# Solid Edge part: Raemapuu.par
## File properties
Author: Kasutaja
Template: Iso Metric Part.par
Last saved by: Kasutaja
Revision: 8
Application: Solid Edge
Accuracy: 0,990
Username: Kasutaja
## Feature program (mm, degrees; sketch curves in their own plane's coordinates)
sketch for "unnamed Protrusion 1" plane through (0, 0, 0) normal (0, -1, 0) x-axis (1, 0, 0)
  line (200, 7.5) -> (-200, 7.5)
  arc centre (-200, 83.2634) radius 75.7634 from (-200, 7.5) to (-269.895, 112.5) cw
  line (-284.895, 112.5) -> (-269.895, 112.5)
  arc centre (-200, 82.5298) radius 90.0298 from (-284.895, 112.5) to (-200, -7.5) ccw
  line (-200, -7.5) -> (200, -7.5)
  arc centre (200, 176.3194) radius 183.8194 from (382.8564, 157.5284) to (200, -7.5) cw
  arc centre (200, 176.323) radius 168.823 from (200, 7.5) to (368.7797, 172.5) ccw
extrude "unnamed Protrusion 1" add finite 12 symmetric
sketch for "ExtrudedCutout_1" #1 plane through (0, 0, 7.5) normal (0, 0, 1) x-axis (1, 0, 0)
  circle centre (-120, 0) radius 2.5
sketch for "ExtrudedCutout_1" #2 plane through (0, 0, 7.5) normal (0, 0, 1) x-axis (1, 0, 0)
  circle centre (0, 0) radius 2.5
sketch for "ExtrudedCutout_1" #3 plane through (0, 0, 7.5) normal (0, 0, 1) x-axis (1, 0, 0)
  circle centre (120, 0) radius 2.5
extrude "ExtrudedCutout_1" cut finite 0.01 symmetric
chamfer "Chamfer_1" setback 3
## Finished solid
Body 1: solid body, 22 faces, 44 edges, 24 vertices.
  Faces by surface: plane 10, cylinder 8, cone 4
  Edges by curve: circle 20, line 20, intersection 4
Bounding box of the edges (mm): 688.108 x 12.000 x 194.319, from (-290.0298, -6, -7.5) to (398.0777, 6, 186.8191).
Cylindrical faces by radius (mm): R2.5 x3, R14.6509 x1, R75.7634 x1, R90.0298 x1, R168.823 x1, R183.8194 x1
Conical faces (half-angle, radius in mm at the cone's reference point): 45 deg R87.0298 x1, 45 deg R90.0298 x1, 45 deg R180.8194 x1, 45 deg R183.8194 x1
Planar faces by outward normal: +y 1, +z 5, -y 1, -z 1, oblique 2
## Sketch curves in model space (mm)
spline (368.7691, 6, 170.0825) -> (368.7604, 6, 170.0634) -> (368.7517, 6, 170.0443)
spline (368.8073, 6, 170.0895) -> (368.7882, 6, 170.086) -> (368.7691, 6, 170.0825)
spline (368.849, 6, 170.1242) -> (368.8282, 6, 170.1069) -> (368.8073, 6, 170.0895)
spline (368.8768, 6, 170.0895) -> (368.8629, 6, 170.1069) -> (368.849, 6, 170.1242)
spline (368.8838, 6, 170.0686) -> (368.8803, 6, 170.079) -> (368.8768, 6, 170.0895)
spline (368.9672, 6, 169.9713) -> (368.9255, 6, 170.02) -> (368.8838, 6, 170.0686)
spline (368.9811, 6, 169.8914) -> (368.9741, 6, 169.9313) -> (368.9672, 6, 169.9713)
spline (369.2418, 6, 169.5612) -> (369.174, 6, 169.6442) -> (368.9811, 6, 169.8914)
spline (369.5928, 6, 169.3492) -> (369.4147, 6, 169.4174) -> (369.2418, 6, 169.5612)
spline (369.7179, 6, 169.3839) -> (369.6554, 6, 169.3665) -> (369.5928, 6, 169.3492)
spline (369.7909, 6, 169.9956) -> (369.7596, 6, 169.6702) -> (369.7179, 6, 169.3839)
spline (369.6588, 6, 170.3015) -> (369.7249, 6, 170.1486) -> (369.7909, 6, 169.9956)
spline (369.7179, 6, 170.4544) -> (369.6884, 6, 170.378) -> (369.6588, 6, 170.3015)
spline (369.6588, 6, 170.8055) -> (369.6636, 6, 170.6443) -> (369.7179, 6, 170.4544)
spline (369.5789, 6, 170.8993) -> (369.6189, 6, 170.8524) -> (369.6588, 6, 170.8055)
spline (369.6032, 6, 170.9584) -> (369.5911, 6, 170.9288) -> (369.5789, 6, 170.8993)
spline (369.5441, 6, 171.0279) -> (369.5737, 6, 170.9931) -> (369.6032, 6, 170.9584)
spline (369.565, 6, 171.0905) -> (369.5546, 6, 171.0592) -> (369.5441, 6, 171.0279)
spline (369.426, 6, 171.2851) -> (369.4955, 6, 171.1878) -> (369.565, 6, 171.0905)
spline (369.4121, 6, 171.2434) -> (369.419, 6, 171.2642) -> (369.426, 6, 171.2851)
spline (369.3704, 6, 171.2851) -> (369.3912, 6, 171.2642) -> (369.4121, 6, 171.2434)
spline (369.3704, 6, 171.4554) -> (369.3704, 6, 171.3702) -> (369.3704, 6, 171.2851)
spline (369.3078, 6, 171.5701) -> (369.3391, 6, 171.5127) -> (369.3704, 6, 171.4554)
spline (369.4121, 6, 171.6674) -> (369.3599, 6, 171.6188) -> (369.3078, 6, 171.5701)
spline (369.6588, 6, 171.6883) -> (369.5524, 6, 171.6875) -> (369.4121, 6, 171.6674)
spline (369.7179, 6, 171.5909) -> (369.6884, 6, 171.6396) -> (369.6588, 6, 171.6883)
spline (369.9647, 6, 171.723) -> (369.8465, 6, 171.6713) -> (369.7179, 6, 171.5909)
spline (370.1211, 6, 171.9003) -> (370.0481, 6, 171.8038) -> (369.9647, 6, 171.723)
spline (370.0829, 6, 172.2409) -> (370.0837, 6, 172.0823) -> (370.1211, 6, 171.9003)
spline (370.0481, 6, 172.2861) -> (370.0655, 6, 172.2635) -> (370.0829, 6, 172.2409)
spline (370.0968, 6, 172.5954) -> (370.0724, 6, 172.4407) -> (370.0481, 6, 172.2861)
spline (370.0481, 6, 172.7483) -> (370.0724, 6, 172.6719) -> (370.0968, 6, 172.5954)
spline (370.1211, 6, 172.9221) -> (370.0846, 6, 172.8352) -> (370.0481, 6, 172.7483)
spline (370.3331, 6, 173.148) -> (370.2271, 6, 173.0351) -> (370.1211, 6, 172.9221)
spline (370.5799, 6, 173.1341) -> (370.4565, 6, 173.1411) -> (370.3331, 6, 173.148)
spline (370.6251, 6, 173.148) -> (370.6025, 6, 173.1411) -> (370.5799, 6, 173.1341)
spline (370.6598, 6, 173.0333) -> (370.6425, 6, 173.0907) -> (370.6251, 6, 173.148)
spline (370.7328, 6, 173.0542) -> (370.6963, 6, 173.0438) -> (370.6598, 6, 173.0333)
spline (370.7919, 6, 172.9221) -> (370.7624, 6, 172.9882) -> (370.7328, 6, 173.0542)
spline (370.7571, 6, 172.9013) -> (370.7745, 6, 172.9117) -> (370.7919, 6, 172.9221)
spline (370.486, 6, 172.015) -> (370.6946, 6, 172.4151) -> (370.7571, 6, 172.9013)
spline (370.5208, 6, 171.9003) -> (370.5034, 6, 171.9576) -> (370.486, 6, 172.015)
spline (370.486, 6, 171.7613) -> (370.5047, 6, 171.8138) -> (370.5208, 6, 171.9003)
spline (370.5799, 6, 171.438) -> (370.533, 6, 171.5996) -> (370.486, 6, 171.7613)
spline (370.6842, 6, 171.3372) -> (370.632, 6, 171.3876) -> (370.5799, 6, 171.438)
spline (370.8718, 6, 170.8993) -> (370.791, 6, 171.0805) -> (370.6842, 6, 171.3372)
spline (370.8162, 6, 170.8611) -> (370.844, 6, 170.8802) -> (370.8718, 6, 170.8993)
spline (370.9101, 6, 170.6873) -> (370.8632, 6, 170.7742) -> (370.8162, 6, 170.8611)
spline (371.3237, 6, 170.1694) -> (371.1534, 6, 170.4579) -> (370.9101, 6, 170.6873)
spline (371.4001, 6, 170.1486) -> (371.3619, 6, 170.159) -> (371.3237, 6, 170.1694)
spline (371.3862, 6, 170.0686) -> (371.3932, 6, 170.1086) -> (371.4001, 6, 170.1486)
spline (371.421, 6, 170.0686) -> (371.4036, 6, 170.0686) -> (371.3862, 6, 170.0686)
spline (371.4558, 6, 170.0304) -> (371.4384, 6, 170.0495) -> (371.421, 6, 170.0686)
spline (371.4488, 6, 169.9956) -> (371.4523, 6, 170.013) -> (371.4558, 6, 170.0304)
spline (371.3862, 6, 169.9504) -> (371.4175, 6, 169.973) -> (371.4488, 6, 169.9956)
spline (371.3167, 6, 169.9574) -> (371.3515, 6, 169.9539) -> (371.3862, 6, 169.9504)
spline (371.2333, 6, 170.0234) -> (371.275, 6, 169.9904) -> (371.3167, 6, 169.9574)
spline (371.2125, 6, 170.0964) -> (371.2229, 6, 170.0599) -> (371.2333, 6, 170.0234)
spline (371.1708, 6, 170.0756) -> (371.1916, 6, 170.086) -> (371.2125, 6, 170.0964)
spline (371.1499, 6, 170.1416) -> (371.1603, 6, 170.1086) -> (371.1708, 6, 170.0756)
spline (371.0873, 6, 170.1764) -> (371.1186, 6, 170.159) -> (371.1499, 6, 170.1416)
spline (371.0873, 6, 170.2424) -> (371.0873, 6, 170.2094) -> (371.0873, 6, 170.1764)
spline (371.0248, 6, 170.2772) -> (371.0561, 6, 170.2598) -> (371.0873, 6, 170.2424)
spline (371.0248, 6, 170.3223) -> (371.0248, 6, 170.2997) -> (371.0248, 6, 170.2772)
spline (370.9483, 6, 170.3606) -> (370.9865, 6, 170.3415) -> (371.0248, 6, 170.3223)
spline (370.639, 6, 170.722) -> (370.7324, 6, 170.6013) -> (370.9483, 6, 170.3606)
spline (370.427, 6, 171.1461) -> (370.5563, 6, 170.946) -> (370.639, 6, 170.722)
spline (370.427, 6, 171.2434) -> (370.427, 6, 171.1947) -> (370.427, 6, 171.1461)
spline (370.3887, 6, 171.2851) -> (370.4078, 6, 171.2642) -> (370.427, 6, 171.2434)
spline (370.3679, 6, 171.3963) -> (370.3783, 6, 171.3407) -> (370.3887, 6, 171.2851)
spline (370.3123, 6, 171.4763) -> (370.3401, 6, 171.4363) -> (370.3679, 6, 171.3963)
spline (370.274, 6, 171.6083) -> (370.2932, 6, 171.5423) -> (370.3123, 6, 171.4763)
spline (370.201, 6, 171.6883) -> (370.2375, 6, 171.6483) -> (370.274, 6, 171.6083)
spline (370.1593, 6, 171.65) -> (370.1802, 6, 171.6692) -> (370.201, 6, 171.6883)
spline (370.1454, 6, 171.5909) -> (370.1524, 6, 171.6205) -> (370.1593, 6, 171.65)
spline (369.8465, 6, 171.3372) -> (369.9934, 6, 171.4693) -> (370.1454, 6, 171.5909)
spline (369.8743, 6, 171.1113) -> (369.8604, 6, 171.2243) -> (369.8465, 6, 171.3372)
spline (369.9091, 6, 171.1113) -> (369.8917, 6, 171.1113) -> (369.8743, 6, 171.1113)
spline (369.9925, 6, 170.9723) -> (369.9508, 6, 171.0418) -> (369.9091, 6, 171.1113)
spline (369.9299, 6, 170.6073) -> (369.9925, 6, 170.7377) -> (369.9925, 6, 170.9723)
spline (369.9438, 6, 170.59) -> (369.9369, 6, 170.5987) -> (369.9299, 6, 170.6073)
spline (369.9299, 6, 170.4926) -> (369.9369, 6, 170.5413) -> (369.9438, 6, 170.59)
spline (370.0273, 6, 170.3015) -> (369.9786, 6, 170.3971) -> (369.9299, 6, 170.4926)
spline (369.6762, 6, 169.2171) -> (369.8183, 6, 169.353) -> (369.9647, 6, 169.4882)
spline (369.6171, 6, 169.2171) -> (369.6506, 6, 169.2171) -> (369.6762, 6, 169.2171)
spline (369.5581, 6, 169.2136) -> (369.5824, 6, 169.214) -> (369.6171, 6, 169.2171)
spline (369.3704, 6, 169.2588) -> (369.446, 6, 169.2362) -> (369.5581, 6, 169.2136)
spline (368.7517, 6, 170.0443) -> (369.0154, 6, 169.6173) -> (369.3704, 6, 169.2588)
spline (371.494, 6, 168.4524) -> (371.4384, 6, 168.1831) -> (371.3828, 6, 167.9137)
spline (371.5357, 6, 168.4907) -> (371.5148, 6, 168.4716) -> (371.494, 6, 168.4524)
spline (371.5739, 6, 168.4524) -> (371.5548, 6, 168.4716) -> (371.5357, 6, 168.4907)
spline (371.845, 6, 168.8) -> (371.7095, 6, 168.6262) -> (371.5739, 6, 168.4524)
spline (371.9389, 6, 168.8556) -> (371.8919, 6, 168.8278) -> (371.845, 6, 168.8)
spline (371.9597, 6, 168.8417) -> (371.9493, 6, 168.8487) -> (371.9389, 6, 168.8556)
spline (372.21, 6, 168.9599) -> (372.0822, 6, 168.9164) -> (371.9597, 6, 168.8417)
spline (372.2656, 6, 169.0085) -> (372.2378, 6, 168.9842) -> (372.21, 6, 168.9599)
spline (372.8425, 6, 169.092) -> (372.5189, 6, 169.0933) -> (372.2656, 6, 169.0085)
spline (373.0928, 6, 169.1823) -> (372.9677, 6, 169.1371) -> (372.8425, 6, 169.092)
spline (373.0789, 6, 169.2171) -> (373.0858, 6, 169.1997) -> (373.0928, 6, 169.1823)
spline (373.0928, 6, 169.2657) -> (373.0858, 6, 169.2414) -> (373.0789, 6, 169.2171)
spline (373.0545, 6, 169.4187) -> (373.0737, 6, 169.3422) -> (373.0928, 6, 169.2657)
spline (373.0337, 6, 169.4187) -> (373.0441, 6, 169.4187) -> (373.0545, 6, 169.4187)
spline (373.0337, 6, 169.4882) -> (373.0337, 6, 169.4534) -> (373.0337, 6, 169.4187)
spline (372.9607, 6, 169.5925) -> (372.9972, 6, 169.5403) -> (373.0337, 6, 169.4882)
spline (372.6549, 6, 169.6724) -> (372.8078, 6, 169.6324) -> (372.9607, 6, 169.5925)
spline (372.5158, 6, 169.8184) -> (372.5853, 6, 169.7454) -> (372.6549, 6, 169.6724)
spline (372.5506, 6, 169.8775) -> (372.5332, 6, 169.8479) -> (372.5158, 6, 169.8184)
spline (372.4811, 6, 169.9157) -> (372.5158, 6, 169.8966) -> (372.5506, 6, 169.8775)
spline (372.4811, 6, 169.9574) -> (372.4811, 6, 169.9365) -> (372.4811, 6, 169.9157)
spline (372.4567, 6, 169.9574) -> (372.4689, 6, 169.9574) -> (372.4811, 6, 169.9574)
spline (372.4394, 6, 170.0165) -> (372.448, 6, 169.9869) -> (372.4567, 6, 169.9574)
spline (372.342, 6, 170.0165) -> (372.3907, 6, 170.0165) -> (372.4394, 6, 170.0165)
spline (372.2864, 6, 170.0512) -> (372.3142, 6, 170.0339) -> (372.342, 6, 170.0165)
spline (372.2447, 6, 170.1486) -> (372.2656, 6, 170.0999) -> (372.2864, 6, 170.0512)
spline (372.21, 6, 170.1103) -> (372.2273, 6, 170.1294) -> (372.2447, 6, 170.1486)
spline (371.9736, 6, 170.5483) -> (372.0918, 6, 170.3293) -> (372.21, 6, 170.1103)
spline (371.9597, 6, 170.6664) -> (371.9667, 6, 170.6073) -> (371.9736, 6, 170.5483)
spline (372.0223, 6, 170.7846) -> (371.991, 6, 170.7255) -> (371.9597, 6, 170.6664)
spline (371.998, 6, 170.9167) -> (372.0101, 6, 170.8506) -> (372.0223, 6, 170.7846)
spline (372.0362, 6, 170.9931) -> (372.0171, 6, 170.9549) -> (371.998, 6, 170.9167)
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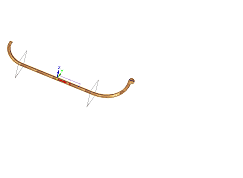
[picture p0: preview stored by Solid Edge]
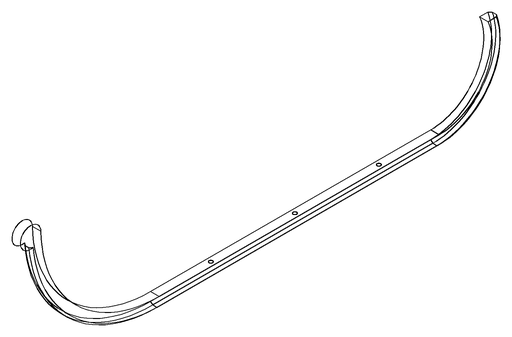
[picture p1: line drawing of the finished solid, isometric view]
